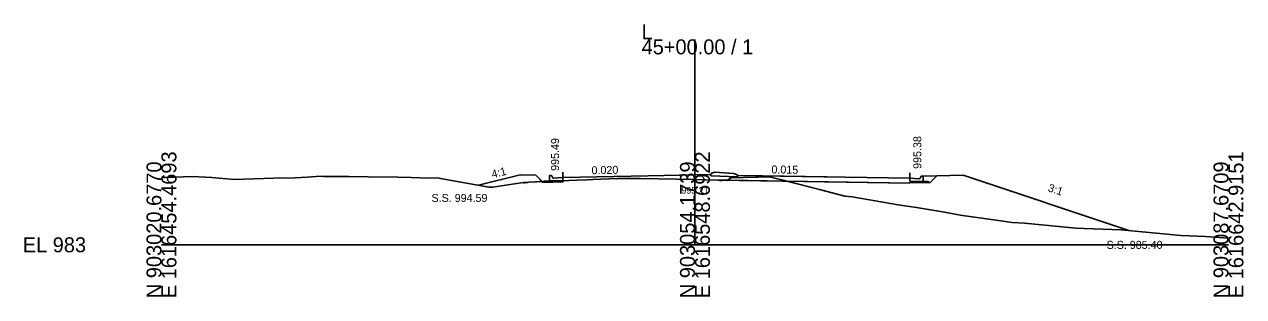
# Model space of a CAD drawing. Extents: x 1009 to 7438, y -1586 to 7964.
# Drawn here: x 4009.2 to 4237.7, y 2914 to 2965 of the extents above; entities that cross this region are included whole.
import ezdxf

# ---------------------------------------------------------------- set-up
doc = ezdxf.new("R2010")
doc.units = 0
for name, color, linetype in [('Exist Cross Section Cell', 7, 'Continuous'), ('Exist XS Center Line Elevation Label', 7, 'Continuous'), ('Exist XS Ground Line', 7, 'Continuous'), ('Prop XS Dump Level', 7, 'Continuous'), ('Prop XS Earthwork Shape', 7, 'Continuous'), ('Prop XS EOT Tick Mark', 7, 'Continuous'), ('Prop XS Finish Grade', 7, 'Continuous'), ('Prop XS Finish Grade CurbGutter', 7, 'Continuous'), ('Prop XS Finish Grade Earthwork', 7, 'Continuous'), ('Prop XS Finish Grade Pavement', 7, 'Continuous'), ('Prop XS Hydro Elevations', 7, 'Continuous'), ('Prop XS Pvmt Edge Slope', 7, 'Continuous'), ('Prop XS SE Text', 7, 'Continuous'), ('Prop XS Side Slope Text', 7, 'Continuous'), ('Prop XS SS Elevation Text', 7, 'Continuous'), ('Prop XS Subgrade CurbGutter', 7, 'Continuous'), ('Prop XS Subgrade Earthwork', 7, 'Continuous')]:
    doc.layers.add(name, color=color, linetype=linetype)

msp = doc.modelspace()

# ---------------------------------------------------------------- linework, layer by layer
at = {"layer": 'Exist Cross Section Cell'}
for p, q in [((4134.89, 2923.73), (4134.89, 2962.19)), ((4034.89, 2923.73), (4134.89, 2923.73)), ((4134.89, 2923.73), (4234.89, 2923.73))]:
    msp.add_line(p, q, dxfattribs=at)
at = {"layer": 'Exist XS Ground Line'}
for p, q in [((4034.89, 2936.32), (4035.59, 2936.36)), ((4035.59, 2936.36), (4036.17, 2936.4)), ((4036.17, 2936.4), (4037.31, 2936.42)), ((4037.31, 2936.42), (4040.73, 2936.51)), ((4040.73, 2936.51), (4044.32, 2936.33)), ((4044.32, 2936.33), (4048.52, 2935.98)), ((4048.52, 2935.98), (4055.87, 2936.2)), ((4055.87, 2936.2), (4059.98, 2936.25)), ((4059.98, 2936.25), (4062.2, 2936.4)), ((4062.2, 2936.4), (4064.73, 2936.55)), ((4064.73, 2936.55), (4065.25, 2936.54)), ((4065.25, 2936.54), (4070.02, 2936.54)), ((4070.02, 2936.54), (4073.66, 2936.45)), ((4073.66, 2936.45), (4079.21, 2936.42)), ((4079.21, 2936.42), (4081.67, 2936.36)), ((4081.67, 2936.36), (4085.1, 2936.19)), ((4085.1, 2936.19), (4086.7, 2936.24)), ((4086.7, 2936.24), (4087.2, 2936.15)), ((4087.2, 2936.15), (4096.26, 2934.52)), ((4096.26, 2934.52), (4097.01, 2934.52)), ((4097.01, 2934.52), (4101.05, 2935.15)), ((4101.05, 2935.15), (4102.75, 2935.42)), ((4102.75, 2935.42), (4103.78, 2935.48)), ((4103.78, 2935.48), (4112.73, 2935.82)), ((4112.73, 2935.82), (4114.78, 2935.9)), ((4114.78, 2935.9), (4115.77, 2935.95)), ((4115.77, 2935.95), (4120.34, 2936.14)), ((4120.34, 2936.14), (4121.18, 2936.14)), ((4121.18, 2936.14), (4124.69, 2936.17)), ((4124.69, 2936.17), (4134.89, 2935.93)), ((4134.89, 2935.93), (4136.85, 2935.89)), ((4136.85, 2935.89), (4139.27, 2935.84)), ((4139.27, 2935.84), (4140.95, 2935.8)), ((4140.95, 2935.8), (4141.68, 2936.29)), ((4141.68, 2936.29), (4146.23, 2936.41)), ((4146.23, 2936.41), (4146.73, 2936.42)), ((4146.73, 2936.42), (4147.43, 2936.43)), ((4147.43, 2936.43), (4149.13, 2936.42)), ((4149.13, 2936.42), (4158.23, 2934.08)), ((4158.23, 2934.08), (4162.99, 2932.82)), ((4162.99, 2932.82), (4164.34, 2932.71)), ((4164.34, 2932.71), (4173.01, 2931.24)), ((4173.01, 2931.24), (4174.24, 2931.04)), ((4174.24, 2931.04), (4176.42, 2930.72)), ((4176.42, 2930.72), (4181.65, 2929.83)), ((4181.65, 2929.83), (4184.63, 2929.3)), ((4184.63, 2929.3), (4191.78, 2928.31)), ((4191.78, 2928.31), (4194.34, 2927.93)), ((4194.34, 2927.93), (4196.65, 2927.78)), ((4196.65, 2927.78), (4206.3, 2926.87)), ((4206.3, 2926.87), (4207.84, 2926.77)), ((4207.84, 2926.77), (4214.76, 2926.54)), ((4214.76, 2926.54), (4225.97, 2925.49)), ((4225.97, 2925.49), (4230.59, 2925.31)), ((4230.59, 2925.31), (4234.89, 2924.99))]:
    msp.add_line(p, q, dxfattribs=at)
at = {"layer": 'Prop XS Dump Level'}
for p, q in [((4126.14, 2936.64), (4134.89, 2936.82)), ((4126.14, 2936.64), (4134.89, 2936.82)), ((4143.64, 2936.68), (4159.64, 2936.44)), ((4143.64, 2936.68), (4159.64, 2936.44)), ((4110.14, 2936.32), (4126.14, 2936.64)), ((4110.14, 2936.32), (4126.14, 2936.64))]:
    msp.add_line(p, q, dxfattribs=at)
at = {"layer": 'Prop XS Earthwork Shape'}
for points in [[(4102.75, 2935.42), (4103.78, 2935.48), (4106.23, 2935.58), (4105.05, 2936.76), (4102.14, 2936.82), (4094.34, 2934.87), (4096.26, 2934.52), (4097.01, 2934.52), (4101.05, 2935.15)], [(4175.16, 2935.29), (4175.16, 2935.37), (4178.91, 2935.32), (4180.24, 2936.65), (4185.16, 2936.75), (4216.2, 2926.4), (4214.76, 2926.54), (4207.84, 2926.77), (4206.3, 2926.87), (4196.65, 2927.78), (4194.34, 2927.93), (4191.78, 2928.31), (4184.63, 2929.3), (4181.65, 2929.83), (4176.42, 2930.72), (4174.24, 2931.04), (4173.01, 2931.24), (4164.34, 2932.71), (4162.99, 2932.82), (4158.23, 2934.08), (4152.19, 2935.64)], [(4106.56, 2935.59), (4106.39, 2935.42), (4106.23, 2935.58)], [(4106.56, 2935.59), (4110.14, 2935.72), (4110.14, 2935.49), (4106.39, 2935.42)], [(4139.27, 2935.83), (4140.95, 2935.8), (4140.97, 2935.81)], [(4149.13, 2936.42), (4152.19, 2935.64), (4140.97, 2935.81), (4141.68, 2936.29), (4146.23, 2936.41), (4146.73, 2936.42), (4147.43, 2936.43)]]:
    msp.add_lwpolyline(points, close=True, dxfattribs=at)
at = {"layer": 'Prop XS EOT Tick Mark'}
for p, q in [((4110.14, 2936.32), (4110.14, 2937.32)), ((4175.16, 2936.2), (4175.16, 2937.2))]:
    msp.add_line(p, q, dxfattribs=at)
at = {"layer": 'Prop XS Finish Grade'}
msp.add_line((4177.66, 2936.59), (4180.24, 2936.65), dxfattribs=at)
at = {"layer": 'Prop XS Finish Grade CurbGutter'}
for p, q in [((4107.64, 2936.7), (4107.89, 2936.7)), ((4107.89, 2936.7), (4108.02, 2936.67)), ((4108.11, 2936.58), (4108.02, 2936.67)), ((4137.89, 2937.05), (4138.64, 2937.3)), ((4137.89, 2936.88), (4137.89, 2937.05)), ((4138.64, 2937.3), (4142.14, 2937.11)), ((4142.89, 2936.86), (4142.14, 2937.11)), ((4142.89, 2936.69), (4142.89, 2936.86)), ((4108.18, 2936.33), (4108.11, 2936.58)), ((4108.27, 2936.24), (4108.18, 2936.33)), ((4108.39, 2936.22), (4108.27, 2936.24)), ((4110.14, 2936.32), (4108.39, 2936.22)), ((4175.16, 2936.2), (4176.91, 2936.11)), ((4176.91, 2936.11), (4177.04, 2936.13)), ((4177.04, 2936.13), (4177.13, 2936.22)), ((4177.13, 2936.22), (4177.2, 2936.47)), ((4177.2, 2936.47), (4177.29, 2936.56)), ((4177.41, 2936.59), (4177.29, 2936.56)), ((4177.66, 2936.59), (4177.41, 2936.59))]:
    msp.add_line(p, q, dxfattribs=at)
at = {"layer": 'Prop XS Finish Grade Earthwork'}
for p, q in [((4102.14, 2936.82), (4094.34, 2934.87)), ((4105.05, 2936.76), (4102.14, 2936.82)), ((4180.24, 2936.65), (4185.16, 2936.75)), ((4185.16, 2936.75), (4216.2, 2926.4))]:
    msp.add_line(p, q, dxfattribs=at)
at = {"layer": 'Prop XS Finish Grade Pavement'}
for p, q in [((4126.14, 2936.64), (4137.89, 2936.88)), ((4142.89, 2936.69), (4175.16, 2936.2)), ((4110.14, 2936.32), (4126.14, 2936.64))]:
    msp.add_line(p, q, dxfattribs=at)
at = {"layer": 'Prop XS Pvmt Edge Slope'}
for p, q in [((4106.64, 2935.67), (4106.39, 2935.42)), ((4107.64, 2935.69), (4106.64, 2935.67)), ((4177.66, 2935.59), (4178.66, 2935.57)), ((4178.66, 2935.57), (4178.91, 2935.32))]:
    msp.add_line(p, q, dxfattribs=at)
at = {"layer": 'Prop XS Subgrade CurbGutter'}
for p, q in [((4107.64, 2935.69), (4107.64, 2936.7)), ((4137.89, 2936.88), (4137.89, 2936.63)), ((4142.89, 2936.69), (4142.89, 2936.44)), ((4110.14, 2935.74), (4107.64, 2935.69)), ((4110.14, 2936.32), (4110.14, 2935.74)), ((4137.89, 2936.63), (4142.89, 2936.44)), ((4175.16, 2936.2), (4175.16, 2935.62)), ((4175.16, 2935.62), (4177.66, 2935.59)), ((4177.66, 2935.59), (4177.66, 2936.59))]:
    msp.add_line(p, q, dxfattribs=at)
at = {"layer": 'Prop XS Subgrade Earthwork'}
for p, q in [((4106.39, 2935.42), (4105.05, 2936.76)), ((4178.91, 2935.32), (4180.24, 2936.65)), ((4110.14, 2935.49), (4106.39, 2935.42)), ((4110.14, 2935.49), (4110.14, 2935.72)), ((4139.27, 2935.83), (4139.27, 2935.84)), ((4139.27, 2935.83), (4175.16, 2935.29)), ((4175.16, 2935.29), (4175.16, 2935.37)), ((4175.16, 2935.37), (4178.91, 2935.32))]:
    msp.add_line(p, q, dxfattribs=at)

# ---------------------------------------------------------------- texts
at = {"layer": 'Exist Cross Section Cell'}
for s, p in [('L', (4124.89, 2962.19)), ('45+00.00 / 1', (4124.89, 2959.39)), ('EL 983', (4008.89, 2922.33))]:
    msp.add_text(s, height=2.8, dxfattribs=at).set_placement(p)
for s, p in [('N 903020.6770', (4034.89, 2913.73)), ('E 1616454.4693', (4037.69, 2913.73)), ('N 903054.1739', (4134.89, 2913.73)), ('E 1616548.6922', (4137.69, 2913.73)), ('N 903087.6709', (4234.89, 2913.73)), ('E 1616642.9151', (4237.69, 2913.73))]:
    msp.add_text(s, height=2.8, rotation=90, dxfattribs=at).set_placement(p)
at = {"layer": 'Exist XS Center Line Elevation Label'}
msp.add_text('995.21', height=1.25, dxfattribs=at).set_placement((4132.34, 2933.31))
at = {"layer": 'Prop XS Dump Level'}
for p in [(4102.75, 2935.12), (4139.27, 2935.54), (4139.27, 2935.54), (4139.27, 2935.54)]:
    msp.add_text('Eop', height=0.3, dxfattribs=at).set_placement(p)
at = {"layer": 'Prop XS Hydro Elevations'}
for s, p in [('995.49', (4109.41, 2937.57)), ('995.38', (4177.32, 2937.94))]:
    msp.add_text(s, height=1.5, rotation=90, dxfattribs=at).set_placement(p)
at = {"layer": 'Prop XS SE Text'}
for s, rotation, p in [('0.020', 1.1458, (4115.52, 2936.93)), ('0.015', 359.1286, (4149.22, 2937.1))]:
    msp.add_text(s, height=1.5, rotation=rotation, dxfattribs=at).set_placement(p)
at = {"layer": 'Prop XS Side Slope Text'}
for s, rotation, p in [('4:1', 14.0362, (4096.96, 2936.19)), ('3:1', 341.5651, (4200.93, 2933.79))]:
    msp.add_text(s, height=1.5, rotation=rotation, dxfattribs=at).set_placement(p)
at = {"layer": 'Prop XS SS Elevation Text'}
for s, p in [('S.S. 994.59', (4085.51, 2931.75)), ('S.S. 985.40', (4212.05, 2922.97))]:
    msp.add_text(s, height=1.5, dxfattribs=at).set_placement(p)

doc.saveas('drawing.dxf')
